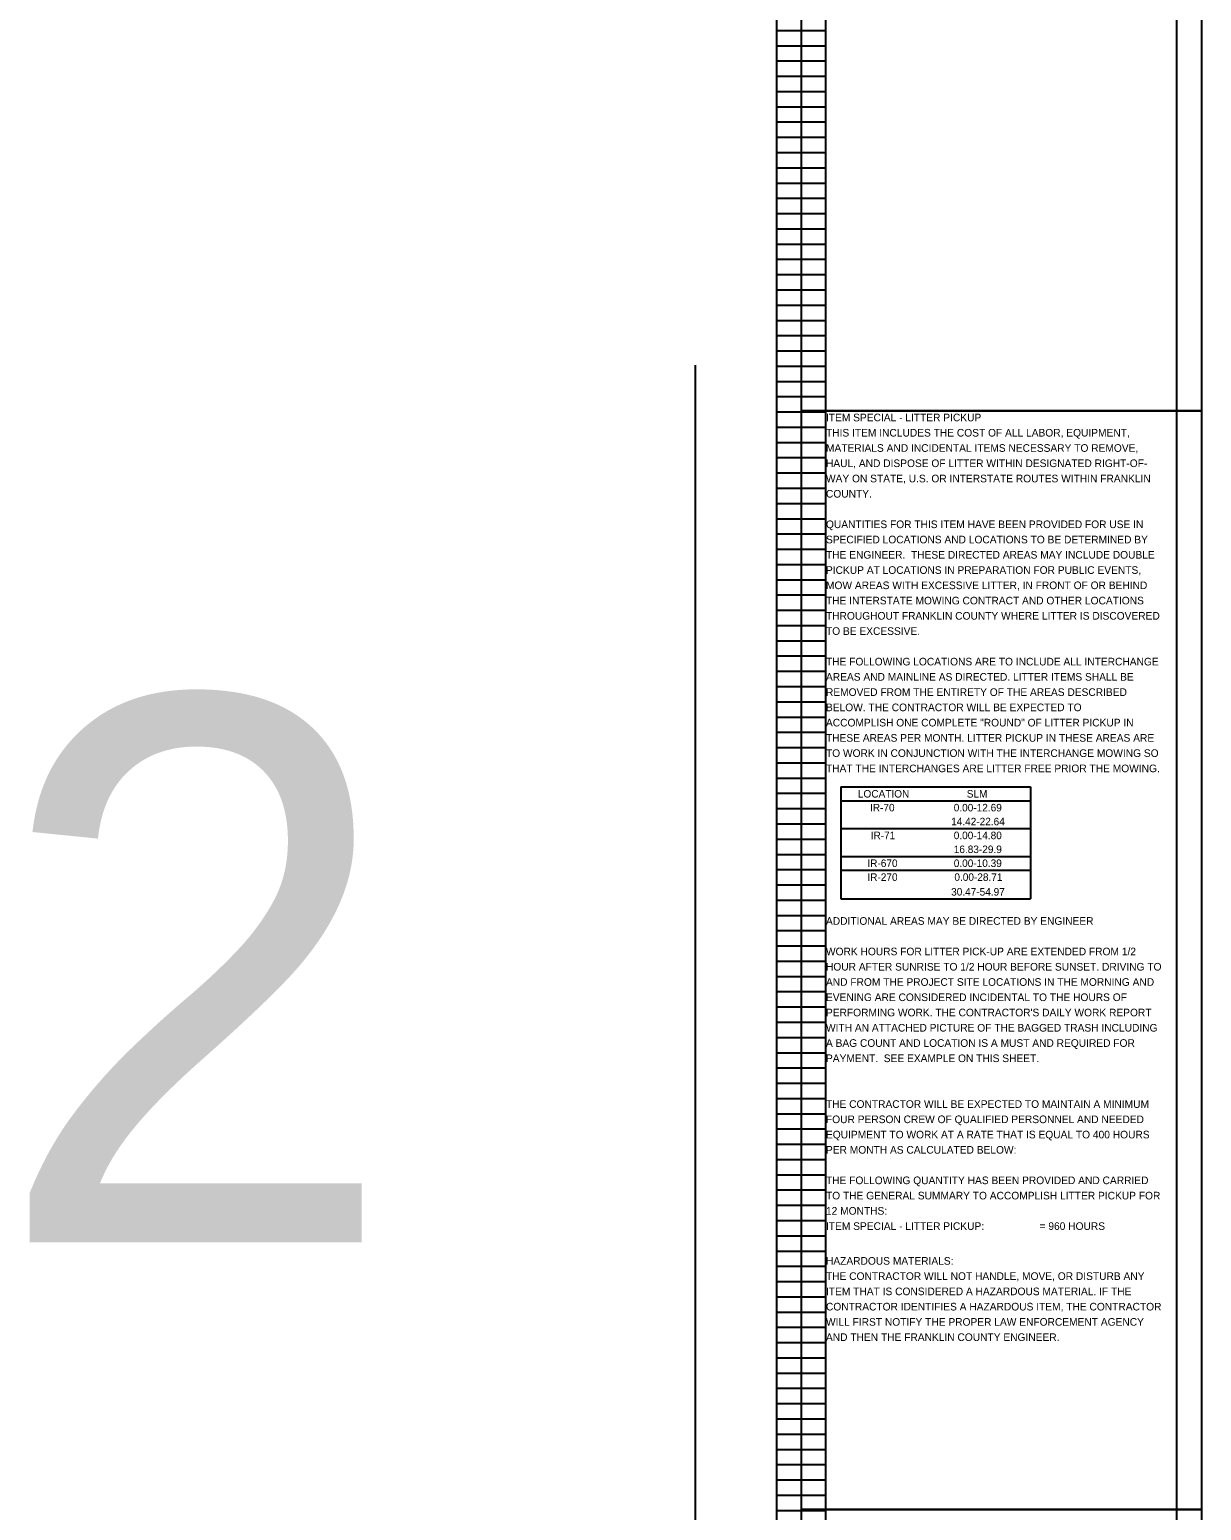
# Model space of a CAD drawing. Extents: x -13 to 322, y -402 to 112.
# Drawn here: x -12.22 to 9.29, y -79.66 to -52.48 of the extents above; entities that cross this region are included whole.
import ezdxf

# ---------------------------------------------------------------- set-up
doc = ezdxf.new("R2010")
doc.units = 0
for name, color, linetype in [('Default', 7, 'Continuous'), ('SC_Scratch1', 7, 'Continuous'), ('SH_Text', 7, 'Continuous')]:
    doc.layers.add(name, color=color, linetype=linetype)

msp = doc.modelspace()

# ---------------------------------------------------------------- linework, layer by layer
at = {"layer": 'Default'}
for p, q in [((2.673, -66.382), (6.153, -66.382)), ((2.673, -66.382), (2.673, -68.437)), ((6.153, -66.382), (6.153, -68.437)), ((2.673, -66.637), (6.153, -66.637)), ((2.673, -67.147), (6.153, -67.147)), ((2.673, -67.657), (6.153, -67.657)), ((2.673, -67.912), (6.153, -67.912)), ((2.673, -68.437), (6.153, -68.437))]:
    msp.add_line(p, q, dxfattribs=at)
at = {"layer": 'SC_Scratch1'}
for p, q in [((1.5, -59.5), (1.5, -39.34)), ((2.4, -59.5), (2.4, -39.34)), ((8.84, -59.5), (8.84, -39.34)), ((1.5, -52.5), (2.4, -52.5)), ((1.5, -52.78), (2.4, -52.78)), ((1.5, -53.06), (2.4, -53.06)), ((1.5, -53.34), (2.4, -53.34)), ((1.5, -53.62), (2.4, -53.62)), ((1.5, -53.9), (2.4, -53.9)), ((1.5, -54.18), (2.4, -54.18)), ((1.5, -54.46), (2.4, -54.46)), ((1.5, -54.74), (2.4, -54.74)), ((1.5, -55.02), (2.4, -55.02)), ((1.5, -55.3), (2.4, -55.3)), ((1.5, -55.58), (2.4, -55.58)), ((1.5, -55.86), (2.4, -55.86)), ((1.5, -56.14), (2.4, -56.14)), ((1.5, -56.42), (2.4, -56.42)), ((1.5, -56.7), (2.4, -56.7)), ((1.5, -56.98), (2.4, -56.98)), ((1.5, -57.26), (2.4, -57.26)), ((1.5, -57.54), (2.4, -57.54)), ((1.5, -57.82), (2.4, -57.82)), ((1.5, -58.1), (2.4, -58.1)), ((1.5, -58.38), (2.4, -58.38)), ((0, -58.64), (0, -80.64)), ((1.5, -58.66), (2.4, -58.66)), ((1.5, -58.94), (2.4, -58.94)), ((1.5, -59.22), (2.4, -59.22)), ((1.5, -59.5), (2.4, -59.5)), ((1.5, -59.5), (2.4, -59.5)), ((1.5, -79.66), (1.5, -59.5)), ((2.4, -79.66), (2.4, -59.5)), ((8.84, -79.66), (8.84, -59.5)), ((1.5, -59.78), (2.4, -59.78)), ((1.5, -60.06), (2.4, -60.06)), ((1.5, -60.34), (2.4, -60.34)), ((1.5, -60.62), (2.4, -60.62)), ((1.5, -60.9), (2.4, -60.9)), ((1.5, -61.18), (2.4, -61.18)), ((1.5, -61.46), (2.4, -61.46)), ((1.5, -61.74), (2.4, -61.74)), ((1.5, -62.02), (2.4, -62.02)), ((1.5, -62.3), (2.4, -62.3)), ((1.5, -62.58), (2.4, -62.58)), ((1.5, -62.86), (2.4, -62.86)), ((1.5, -63.14), (2.4, -63.14)), ((1.5, -63.42), (2.4, -63.42)), ((1.5, -63.7), (2.4, -63.7)), ((1.5, -63.98), (2.4, -63.98)), ((1.5, -64.26), (2.4, -64.26)), ((1.5, -64.54), (2.4, -64.54)), ((1.5, -64.82), (2.4, -64.82)), ((1.5, -65.1), (2.4, -65.1)), ((1.5, -65.38), (2.4, -65.38)), ((1.5, -65.66), (2.4, -65.66)), ((1.5, -65.94), (2.4, -65.94)), ((1.5, -66.22), (2.4, -66.22)), ((1.5, -66.5), (2.4, -66.5)), ((1.5, -66.78), (2.4, -66.78)), ((1.5, -67.06), (2.4, -67.06)), ((1.5, -67.34), (2.4, -67.34)), ((1.5, -67.62), (2.4, -67.62)), ((1.5, -67.9), (2.4, -67.9)), ((1.5, -68.18), (2.4, -68.18)), ((1.5, -68.46), (2.4, -68.46)), ((1.5, -68.74), (2.4, -68.74)), ((1.5, -69.02), (2.4, -69.02)), ((1.5, -69.3), (2.4, -69.3)), ((1.5, -69.58), (2.4, -69.58)), ((1.5, -69.86), (2.4, -69.86)), ((1.5, -70.14), (2.4, -70.14)), ((1.5, -70.42), (2.4, -70.42)), ((1.5, -70.7), (2.4, -70.7)), ((1.5, -70.98), (2.4, -70.98)), ((1.5, -71.26), (2.4, -71.26)), ((1.5, -71.54), (2.4, -71.54)), ((1.5, -71.82), (2.4, -71.82)), ((1.5, -72.1), (2.4, -72.1)), ((1.5, -72.38), (2.4, -72.38)), ((1.5, -72.66), (2.4, -72.66)), ((1.5, -72.94), (2.4, -72.94)), ((1.5, -73.22), (2.4, -73.22)), ((1.5, -73.5), (2.4, -73.5)), ((1.5, -73.78), (2.4, -73.78)), ((1.5, -74.06), (2.4, -74.06)), ((1.5, -74.34), (2.4, -74.34)), ((1.5, -74.62), (2.4, -74.62)), ((1.5, -74.9), (2.4, -74.9)), ((1.5, -75.18), (2.4, -75.18)), ((1.5, -75.46), (2.4, -75.46)), ((1.5, -75.74), (2.4, -75.74)), ((1.5, -76.02), (2.4, -76.02)), ((1.5, -76.3), (2.4, -76.3)), ((1.5, -76.58), (2.4, -76.58)), ((1.5, -76.86), (2.4, -76.86)), ((1.5, -77.14), (2.4, -77.14)), ((1.5, -77.42), (2.4, -77.42)), ((1.5, -77.7), (2.4, -77.7)), ((1.5, -77.98), (2.4, -77.98)), ((1.5, -78.26), (2.4, -78.26)), ((1.5, -78.54), (2.4, -78.54)), ((1.5, -78.82), (2.4, -78.82)), ((1.5, -79.1), (2.4, -79.1)), ((1.5, -79.38), (2.4, -79.38)), ((1.5, -79.66), (2.4, -79.66)), ((1.5, -79.66), (2.4, -79.66)), ((1.5, -99.82), (1.5, -79.66)), ((2.4, -99.82), (2.4, -79.66)), ((8.84, -99.82), (8.84, -79.66))]:
    msp.add_line(p, q, dxfattribs=at)
for points in [[(1.95, -39.323), (9.29, -39.323), (9.29, -59.483), (1.95, -59.483)], [(1.95, -59.483), (9.29, -59.483), (9.29, -79.643), (1.95, -79.643)], [(1.95, -79.643), (9.29, -79.643), (9.29, -99.803), (1.95, -99.803)]]:
    msp.add_lwpolyline(points, close=True, dxfattribs=at)

# ---------------------------------------------------------------- texts
at = {"layer": 'Default'}
for s, p in [('LOCATION', (2.986, -66.578)), ('SLM', (4.984, -66.578)), ('IR-70', (3.208, -66.832)), ('0.00-12.69', (4.745, -66.832)), ('14.42-22.64', (4.697, -67.087)), ('IR-71', (3.22, -67.342)), ('0.00-14.80', (4.745, -67.342)), ('16.83-29.9', (4.745, -67.597)), ('IR-670', (3.16, -67.852)), ('0.00-10.39', (4.745, -67.852)), ('IR-270', (3.16, -68.107)), ('0.00-28.71', (4.757, -68.107)), ('30.47-54.97', (4.697, -68.377))]:
    msp.add_text(s, height=0.138, dxfattribs=at).set_placement(p)
at = {"layer": 'SH_Text'}
for s, height, p in [('ITEM SPECIAL - LITTER PICKUP', 0.14, (2.4, -59.673)), ('THIS ITEM INCLUDES THE COST OF ALL LABOR, EQUIPMENT, ', 0.14, (2.4, -59.953)), ('MATERIALS AND INCIDENTAL ITEMS NECESSARY TO REMOVE, ', 0.14, (2.4, -60.233)), ('HAUL, AND DISPOSE OF LITTER WITHIN DESIGNATED RIGHT-OF-', 0.14, (2.4, -60.513)), ('WAY ON STATE, U.S. OR INTERSTATE ROUTES WITHIN FRANKLIN ', 0.14, (2.4, -60.793)), ('COUNTY.', 0.14, (2.4, -61.073)), ('QUANTITIES FOR THIS ITEM HAVE BEEN PROVIDED FOR USE IN ', 0.14, (2.4, -61.633)), ('SPECIFIED LOCATIONS AND LOCATIONS TO BE DETERMINED BY ', 0.14, (2.4, -61.913)), ('THE ENGINEER.  THESE DIRECTED AREAS MAY INCLUDE DOUBLE ', 0.14, (2.4, -62.193)), ('PICKUP AT LOCATIONS IN PREPARATION FOR PUBLIC EVENTS, ', 0.14, (2.4, -62.473)), ('MOW AREAS WITH EXCESSIVE LITTER, IN FRONT OF OR BEHIND ', 0.14, (2.4, -62.753)), ('THE INTERSTATE MOWING CONTRACT AND OTHER LOCATIONS ', 0.14, (2.4, -63.033)), ('THROUGHOUT FRANKLIN COUNTY WHERE LITTER IS DISCOVERED ', 0.14, (2.4, -63.313)), ('TO BE EXCESSIVE.', 0.14, (2.4, -63.593)), ('THE FOLLOWING LOCATIONS ARE TO INCLUDE ALL INTERCHANGE ', 0.14, (2.4, -64.153)), ('AREAS AND MAINLINE AS DIRECTED. LITTER ITEMS SHALL BE ', 0.14, (2.4, -64.433)), ('2', 10, (-12.888, -74.741)), ('REMOVED FROM THE ENTIRETY OF THE AREAS DESCRIBED ', 0.14, (2.4, -64.713)), ('BELOW. THE CONTRACTOR WILL BE EXPECTED TO ', 0.14, (2.4, -64.993)), ('ACCOMPLISH ONE COMPLETE "ROUND" OF LITTER PICKUP IN ', 0.14, (2.4, -65.273)), ('THESE AREAS PER MONTH. LITTER PICKUP IN THESE AREAS ARE ', 0.14, (2.4, -65.553)), ('TO WORK IN CONJUNCTION WITH THE INTERCHANGE MOWING SO ', 0.14, (2.4, -65.833)), ('THAT THE INTERCHANGES ARE LITTER FREE PRIOR THE MOWING.', 0.14, (2.4, -66.113)), ('ADDITIONAL AREAS MAY BE DIRECTED BY ENGINEER', 0.14, (2.4, -68.913)), ('WORK HOURS FOR LITTER PICK-UP ARE EXTENDED FROM 1/2 ', 0.14, (2.4, -69.473)), ('HOUR AFTER SUNRISE TO 1/2 HOUR BEFORE SUNSET. DRIVING TO ', 0.14, (2.4, -69.753)), ('AND FROM THE PROJECT SITE LOCATIONS IN THE MORNING AND ', 0.14, (2.4, -70.033)), ('EVENING ARE CONSIDERED INCIDENTAL TO THE HOURS OF ', 0.14, (2.4, -70.313)), ("PERFORMING WORK. THE CONTRACTOR'S DAILY WORK REPORT ", 0.14, (2.4, -70.593)), ('WITH AN ATTACHED PICTURE OF THE BAGGED TRASH INCLUDING ', 0.14, (2.4, -70.873)), ('A BAG COUNT AND LOCATION IS A MUST AND REQUIRED FOR ', 0.14, (2.4, -71.153)), ('PAYMENT.  SEE EXAMPLE ON THIS SHEET.', 0.14, (2.4, -71.433)), ('THE CONTRACTOR WILL BE EXPECTED TO MAINTAIN A MINIMUM ', 0.14, (2.4, -72.273)), ('FOUR PERSON CREW OF QUALIFIED PERSONNEL AND NEEDED ', 0.14, (2.4, -72.553)), ('EQUIPMENT TO WORK AT A RATE THAT IS EQUAL TO 400 HOURS ', 0.14, (2.4, -72.833)), ('PER MONTH AS CALCULATED BELOW:', 0.14, (2.4, -73.113)), ('THE FOLLOWING QUANTITY HAS BEEN PROVIDED AND CARRIED ', 0.14, (2.4, -73.673)), ('TO THE GENERAL SUMMARY TO ACCOMPLISH LITTER PICKUP FOR ', 0.14, (2.4, -73.953)), ('12 MONTHS:', 0.14, (2.4, -74.233)), ('ITEM SPECIAL - LITTER PICKUP:', 0.14, (2.4, -74.513)), ('= 960 HOURS', 0.14, (6.32, -74.513)), ('HAZARDOUS MATERIALS:', 0.14, (2.4, -75.151)), ('THE CONTRACTOR WILL NOT HANDLE, MOVE, OR DISTURB ANY ', 0.14, (2.4, -75.431)), ('ITEM THAT IS CONSIDERED A HAZARDOUS MATERIAL. IF THE ', 0.14, (2.4, -75.711)), ('CONTRACTOR IDENTIFIES A HAZARDOUS ITEM, THE CONTRACTOR ', 0.14, (2.4, -75.991)), ('WILL FIRST NOTIFY THE PROPER LAW ENFORCEMENT AGENCY ', 0.14, (2.4, -76.271)), ('AND THEN THE FRANKLIN COUNTY ENGINEER.', 0.14, (2.4, -76.551))]:
    msp.add_text(s, height=height, dxfattribs=at).set_placement(p)

doc.saveas('drawing.dxf')
